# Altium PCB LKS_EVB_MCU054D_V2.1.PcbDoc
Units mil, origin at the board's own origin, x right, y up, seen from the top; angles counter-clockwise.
Board outline 2625 x 1560 mil, 2 copper layers (Top Layer, Bottom Layer); 32 components, 49 nets, 170 pads, 61 vias.
Unrouted connection lines stored in the file: 4.
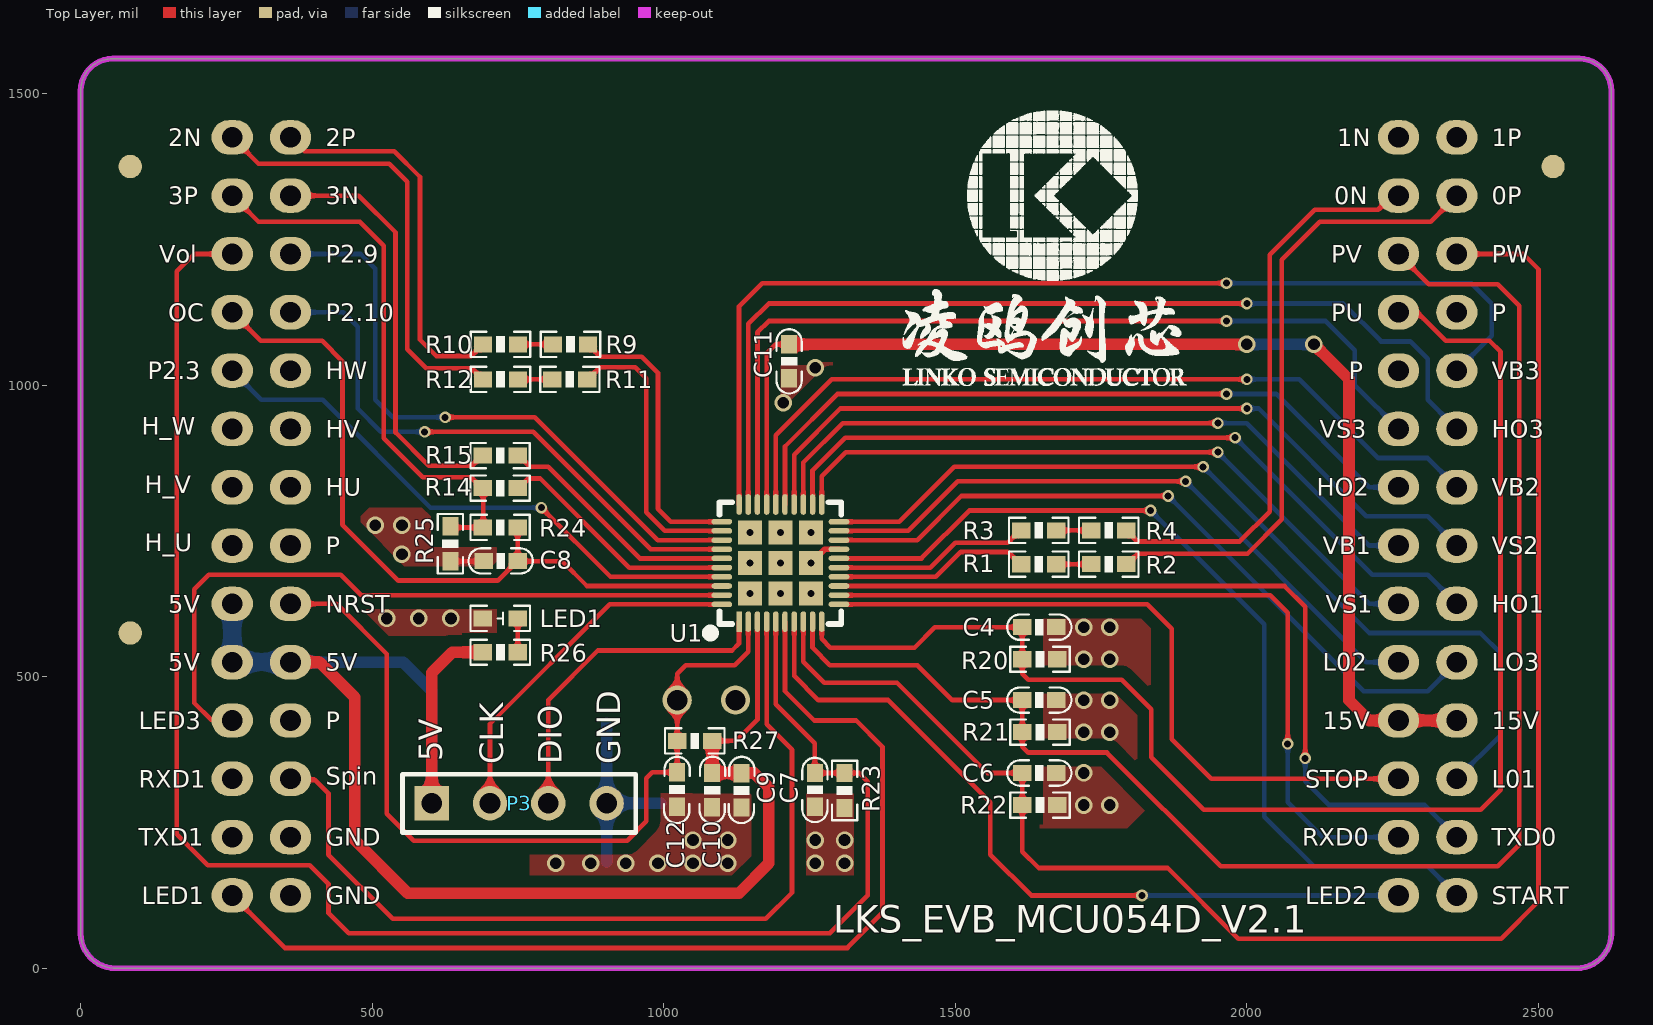
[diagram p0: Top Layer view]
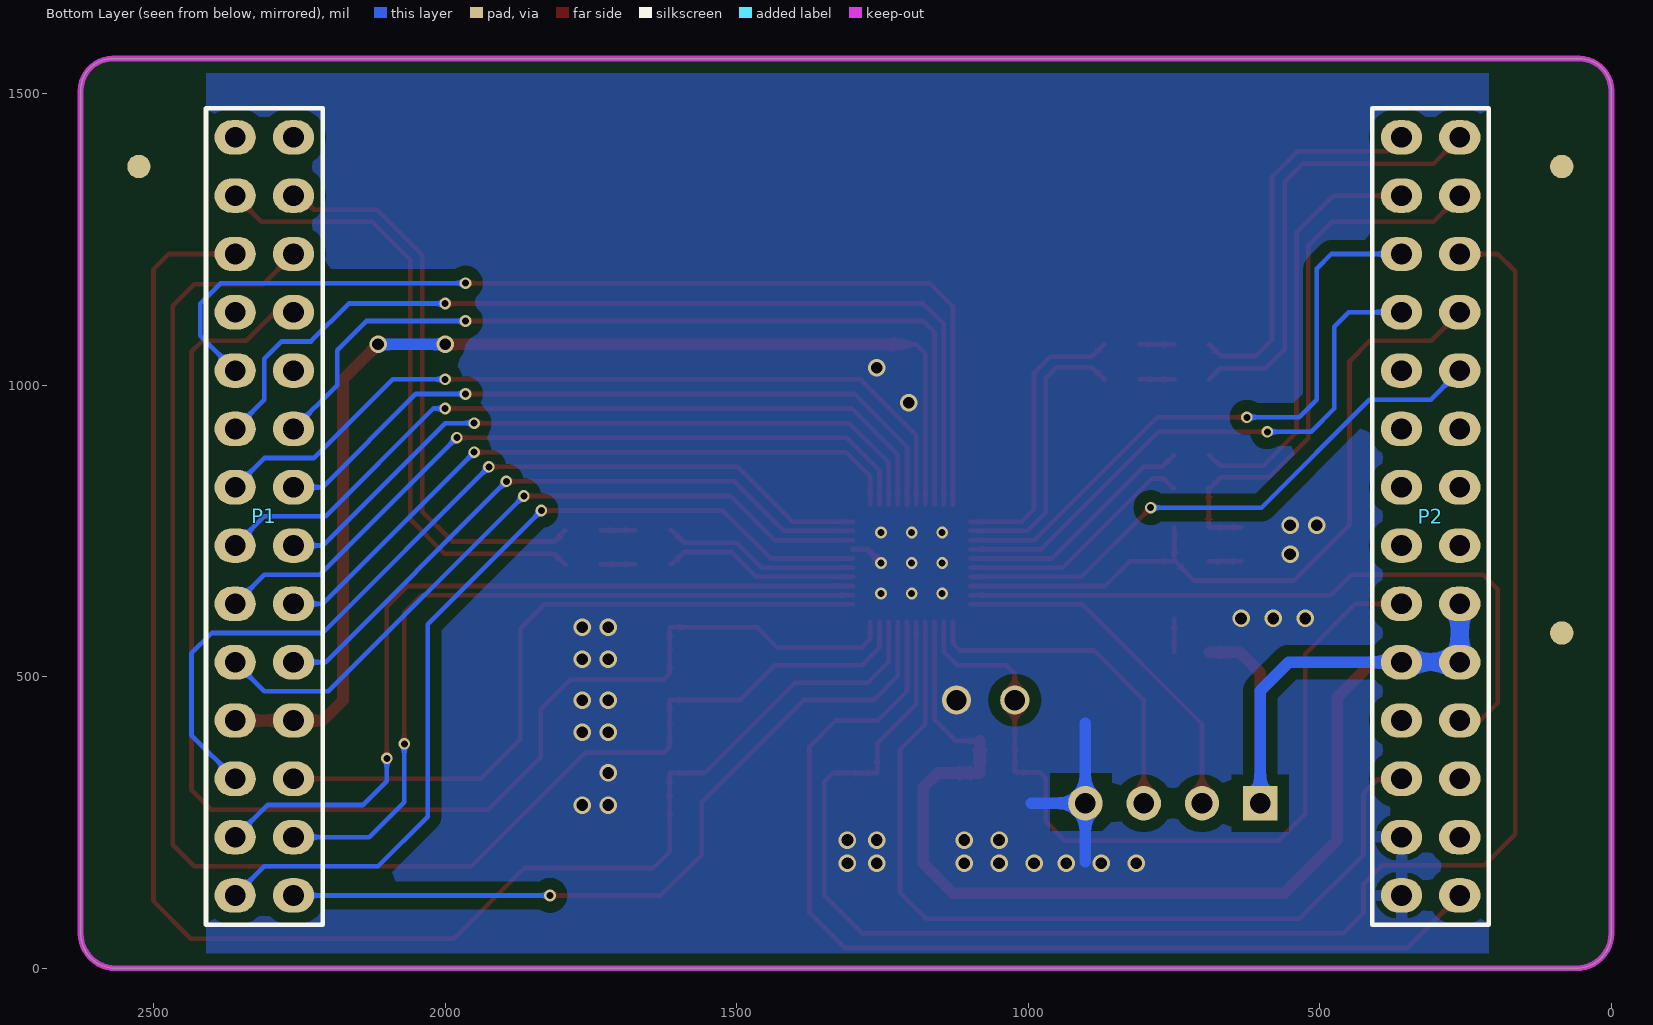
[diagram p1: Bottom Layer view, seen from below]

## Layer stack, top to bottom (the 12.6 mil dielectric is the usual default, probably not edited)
Top Solder: solder mask 0.4, Solder Resist, Dk 3.5
Top Layer: signal copper 1.4
Dielectric1: dielectric 12.6, FR-4, Dk 4.8
Bottom Layer: signal copper 1.4
Bottom Solder: solder mask 0.4, Solder Resist, Dk 3.5

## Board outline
0,60 ccw(c60,60) 60,0 2565,0 ccw(c2565,60) 2625,60 2625,1505 ccw(c2570,1505) 2570,1560 55,1560 ccw(c55,1505) 0,1505

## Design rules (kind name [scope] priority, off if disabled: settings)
Clearance Clearance_1 [InPolygon] p1: gap=20 ignorepadtopadclearanceinfootprint=FALSE except(0: Arc-Hole Track-Hole SMDPad-Hole THPad-Hole Via-Hole Fill-Hole Poly-Hole Region-Hole Text-Hole)
Clearance [All] p2 off: gap=10 ignorepadtopadclearanceinfootprint=FALSE except(0: Arc-Hole Track-Hole SMDPad-Hole THPad-Hole Via-Hole Fill-Hole Poly-Hole Region-Hole Text-Hole)
ComponentClearance [All] p1: gap=0 collisioncheckmode=3 verticalgap=0 showdistances=FALSE
FabricationTestpoint [(IsPad And (OnTopLayer Or OnBottomLayer))] p1: side=3 testpointundercomponent=TRUE minsize=40 maxsize=100 preferedsize=60 minholesize=0 maxholesize=40 preferedholesize=32 testpointgrid=1 allowsidetop=TRUE allowsidebottom=TRUE usegrid=TRUE gridtolerance=0.01
HoleSize [All] p1: absolutevalues=TRUE maxlimit=100 minlimit=0 maxpercent=80.000 minpercent=20.000
PolygonConnect PolygonConnect_1 [HasFootprint('HDR 2X14 顶层') vs InNet('GND')] p1: connectstyle=Relief reliefconductorwidth=20 reliefentries=4 polygonreliefangle="90 Angle" airgapwidth=10
PolygonConnect [All] p2: connectstyle=Direct reliefconductorwidth=30 reliefentries=4 polygonreliefangle="90 Angle" airgapwidth=10
RoutingVias [All] p1: holewidth=28 width=50 viastyle="Through Hole" minholewidth=0 minwidth=10 maxholewidth=28 maxwidth=100
SilkToSolderMaskClearance SilkscreenOverComponentPads [IsPad] p1: minsilkscreentomaskgap=10 clearancetoexposedcopper=TRUE
SolderMaskExpansion [All] p1: expansion=4 istentingtop=FALSE
Width [All] p1: maxlimit=100 minlimit=2 preferedwidth=10
26 further rules are at their usual default settings.

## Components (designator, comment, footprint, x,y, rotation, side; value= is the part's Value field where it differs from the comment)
C4 "1nF/16V" 0603C#1 1644,585 r0 top
C5 "1nF/16V" 0603C#1 1644,460 r0 top
C6 "1nF/16V" 0603C#1 1644,335 r0 top
C7 "100nF/50V" 0603C#1 1259.18,305.95 r90 top
C8 "1nF/50V" 0603C#1 720.35,698.65 r0 top
C9 "10uF/16V" 0603C#2 1133,275.76 r90 top
C10 "100nF/50V" 0603C#2 1083,275.94 r90 top
C11 "4.7uF/25V" 0603C#1 1215,1040.95 r90 top
C12 "100nF/50V" 0603C#2 1023,336 r270 top
LED1 "LED" "LED 0603R" 719.69,600 r180 top
P1 "Header 14X2A" "HDR 2X14 顶层" 2310,775 r180 bottom locked
P2 "Header 14X2A" "HDR 2X14 顶层" 310,775 r180 bottom locked
P3 "Header 4" "HDR 1X4" 602,283 r0 top
R1 "20K" 0603R 1643,692.98 r180 top value=K
R2 "20K" 0603R 1763,693 r180 top value=K
R3 "20K" 0603R 1643,751 r180 top value=K
R4 "20K" 0603R 1763,751 r180 top value=K
R9 "20K" 0603R 839.97,1070.01 r0 top value=K
R10 "20K" 0603R 719.95,1070.01 r0 top value=K
R11 "20K" 0603R 838.95,1010.01 r0 top value=K
R12 "20K" 0603R 719.95,1010.01 r0 top value=K
R14 "1K" 0603R 719.4,823.35 r0 top value=K
R15 "1K" 0603R 719.4,879.35 r0 top value=K
R20 "1K" 0603R 1645,530 r0 top value=K
R21 "1K" 0603R 1645,405 r0 top value=K
R22 "1K" 0603R 1645,280 r0 top value=K
R23 "1K" 0603R 1310,305 r90 top value=K
R24 "1K" 0603R 719.4,756 r180 top value=K
R25 "10R" 0603R 634,727.94 r270 top value=K
R26 "3.3K" 0603R 719.69,542 r180 top value=330
R27 "20K" 0603R 1053,390 r180 top value=330
U1 "LKS32MC054DF6Q8" QFN40 1200,695 r90 top locked

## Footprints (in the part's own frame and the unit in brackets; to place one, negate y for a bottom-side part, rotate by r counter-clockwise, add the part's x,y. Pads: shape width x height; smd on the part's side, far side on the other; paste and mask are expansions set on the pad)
0603C#1 [mm] "电容"
  rect 0.8x0.7 smd: 1(-0.737,0) 2(0.738,0)
  silkscreen extent -1.4,-0.55 1.4,0.55, body extent -0.8,-0.41 0.8,0.41, height 0.81
0603C#2 [mm]
  rect 0.8x0.7 smd: 1(0,0) 2(1.5,0)
  silkscreen extent -0.68,-0.57 2.21,0.55
0603R [mm] "电阻"
  rect 0.8x0.7 smd: 1(-0.762,0) 2(0.762,0)
  silkscreen extent -1.3,-0.55 1.3,0.55, body extent -0.8,-0.4 0.8,0.4, height 0.45
"HDR 1X4" [mm] "单排针 2.54mm"
  rect 1.5x1.5 hole 0.9: 1(0,0)
  round 1.5 hole 0.9: 2(2.54,0) 3(5.08,0) 4(7.62,0)
  silkscreen extent -1.27,-1.27 8.89,1.27, body extent -1.27,-1.27 8.89,1.27, height 8.5
"HDR 2X14 顶层" [mm] "双排针 2.54mm 顶层"
  oval 1.8x1.5 hole 0.9: 1(1.27,16.51) 2(1.27,13.97) 3(1.27,11.43) 4(1.27,8.89) 5(1.27,6.35) 6(1.27,3.81) 7(1.27,1.27) 8(1.27,-1.27) 9(1.27,-3.81) 10(1.27,-6.35) 11(1.27,-8.89) 12(1.27,-11.43) 13(1.27,-13.97) 14(1.27,-16.51) 15(-1.27,16.51) 16(-1.27,13.97) 17(-1.27,11.43) 18(-1.27,8.89) 19(-1.27,6.35) 20(-1.27,3.81) 21(-1.27,1.27) 22(-1.27,-1.27) 23(-1.27,-3.81) 24(-1.27,-6.35) 25(-1.27,-8.89) 26(-1.27,-11.43) 27(-1.27,-13.97) 28(-1.27,-16.51)
  silkscreen extent -2.54,-17.78 2.54,17.78, body extent -2.54,-17.78 2.54,17.78, height 8.5
"LED 0603R" [mm] "LED"
  rect 0.8x0.7 smd: 1(-0.762,0) 2(0.762,0)
  silkscreen extent -1.3,-0.55 1.3,0.55, body extent -0.8,-0.4 0.8,0.4, height 0.47
QFN40 [mm] "LINKO-084D"
  rect 1.05x1.05 smd: 0(-1.33,-1.33) 0(-1.33,0) 0(-1.33,1.33) 0(0,1.33) 0(0,0) 0(0,-1.33) 0(1.33,-1.33) 0(1.33,0) 0(1.33,1.33)
  rect 0.9x0.24 smd: 1(-2.55,1.8)
  oval 0.9x0.24 smd: 2(-2.55,1.4) 3(-2.55,1) 4(-2.55,0.6) 5(-2.55,0.2) 6(-2.55,-0.2) 7(-2.55,-0.6) 8(-2.55,-1) 9(-2.55,-1.4) 10(-2.55,-1.8) 21(2.55,-1.8) 22(2.55,-1.4) 23(2.55,-1) 24(2.55,-0.6) 25(2.55,-0.2) 26(2.55,0.2) 27(2.55,0.6) 28(2.55,1) 29(2.55,1.4) 30(2.55,1.8)
  oval 0.24x0.9 smd: 11(-1.8,-2.55) 12(-1.4,-2.55) 13(-1,-2.55) 14(-0.6,-2.55) 15(-0.2,-2.55) 16(0.2,-2.55) 17(0.6,-2.55) 18(1,-2.55) 19(1.4,-2.55) 20(1.8,-2.55) 31(1.8,2.55) 32(1.4,2.55) 33(1,2.55) 34(0.6,2.55) 35(0.2,2.55) 36(-0.2,2.55) 37(-0.6,2.55) 38(-1,2.55) 39(-1.4,2.55) 40(-1.8,2.55)
  silkscreen extent -3.16,-2.65 2.65,3.16, body extent -3,-3 3,3, height 0.9

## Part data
C4 C5 C6: library part CAP, "Capacitor"
C7 C8 C9 C10 C11 C12: library part C, "Capacitor"
LED1: "LED_Light"
P1 P2: "Header, 14-Pin, Dual row"
P3: "Header, 4-Pin"
R1 R2 R3 R4 R9 R10 R11 R12 R14 R15 R20 R21 R22 R23 R24 R25 R26 R27: library part Res, "Resistor"
U1: "芯片"

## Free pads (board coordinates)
  round 50 hole 35: 0(1123,460) 1(1023,460)
  round 40 all layers, no hole: 1(85,1375) 2(85,575) 3(2525,1375)

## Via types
v1: diameter 30, hole 20, Top Layer to Bottom Layer, 33 vias
v2: diameter 20, hole 12, Top Layer to Bottom Layer, 28 vias

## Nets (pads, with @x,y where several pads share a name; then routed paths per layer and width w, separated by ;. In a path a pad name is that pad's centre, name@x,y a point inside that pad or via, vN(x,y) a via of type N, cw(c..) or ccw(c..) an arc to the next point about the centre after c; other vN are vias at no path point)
+5V: C9.2 C10.2 P2.9 P2.10 P2.24 P3.1 R26.2 R27.1 U1.3 | length 2683.2
  Top Layer w8: R27.1 1124,390 1160.63,426.63 U1.3
  Top Layer w20: P2.24 410,525 470,465 470,220 561,129 1129,129 1180,180 1180,310.26 1155.44,334.82 C9.2 ; P3.1 602,507 637,542 R26.2 ; C10.2 R27.1 ; C10.2@1083.09,334.91 C9.2@1132.91,334.91
  Bottom Layer w20: P2.24 553,525 602,476 P3.1
  Bottom Layer w30: P2.9 P2.10 P2.24
+15V: C11.2 P1.11 P1.25 U1.27 | length 2038.5
  Top Layer w8: U1.27 1176.38,1054.57 1191.81,1070 C11.2
  Top Layer w20: C11.2 v1(2000,1070) ; v1(2115,1070) 2175,1010 2175,460 2210,425 P1.11 P1.25
  Bottom Layer w20: v1(2000,1070) v1(2115,1070)
GND: C4.2 C5.2 C6.2 C7.1 C8.1 C9.1 C10.1 C11.1 C12.2 LED1.2 P2.16 P2.27 P2.28 P3.4 pad.0 R15.1 R20.2 R21.2 R22.2 R23.1 R25.2 U1.0 U1.17 | length 1175.1
  Top Layer w8: P2.16 477,1325 540,1262 540,919 597,862 671.03,862 688.38,879.35 R15.1@690.35,879.35 ; R25.2 690.94,697.94 C8.1@691,698
  Top Layer w10: v2(1252.36,695) 1275.98,718.62 U1.17
  Bottom Layer w20: 902,183 P3.4 ; 902,420 P3.4 ; 995,283 P3.4
  other v1: 815,180 875,180 935,180 990,180 1050,180 1110,180 1260,180 1310,180 1050,220 1110,220 1260,220 1310,220 1720,280 1765,280 1720,335 1720,405 1765,405 1720,460 1765,460 1720,530 1765,530 1720,585 1765,585 525,600 580,600 635,600 551,710 505,760 551,760 1205,970 1260,1030
  other v2: 1147.64,642.64 1200,642.64 1252.36,642.64 1147.64,695 1200,695 1147.64,747.36 1200,747.36 1252.36,747.36
HO1: P1.23 U1.22 | length 1304.8
  Top Layer w8: U1.22 1255.12,854.12 1311,910 v2(1980,910)
  Bottom Layer w8: v2(1980,910) 2215,675 2310,675 P1.23
HO2: P1.7 U1.25 | length 1255.2
  Top Layer w8: U1.25 1207.87,894.87 1298,985 v2(1965,985)
  Bottom Layer w8: v2(1965,985) 2050,985 2210,825 P1.7
HO3: P1.20 U1.29 | length 1669.3
  Top Layer w8: U1.29 1144.88,1105 1179.88,1140 v2(2000,1140)
  Bottom Layer w8: v2(2000,1140) 2165,1140 2230,1075 2280,1075 2310,1045 2310,975 P1.20
LED1: P2.14 U1.6 | length 1788.2
  Top Layer w8: P2.14 350,35 1315,35 1375,95 1375,380 1330,425 1257.87,425 1207.87,475 U1.6
LED2: P1.14 U1.7 | length 1338.2
  Top Layer w8: U1.7 1223.62,501.38 1265,460 1385,460 1560,285 1560,195 1630,125 v2(1820,125)
  Bottom Layer w8: v2(1820,125) P1.14
LED3: P2.11 U1.39 | length 1201.9
  Top Layer w8: P2.11 258.16,426.84 223.16,426.84 195,455 195,650 220,675 446,675 481.12,639.88 U1.39
LO1: P1.26 U1.20 | length 1552.2
  Top Layer w8: U1.20 1403.87,765.87 1498,860 v2(1925,860)
  Bottom Layer w8: v2(1925,860) 2210,575 2400,575 2435,540 2435,400 P1.26
LO2: P1.10 U1.19 | length 1123.2
  Top Layer w8: U1.19 1419.12,750.12 1504,835 v2(1895,835)
  Bottom Layer w8: v2(1895,835) 2205,525 P1.10
LO3: P1.24 U1.18 | length 1250.4
  Top Layer w8: U1.18 1434.37,734.37 1510,810 v2(1865,810)
  Bottom Layer w8: v2(1865,810) 2200,475 2310,475 P1.24
NetLED1_1: LED1.1 R26.1 | length 58
  Top Layer w8: R26.1 LED1.1
NetR1_1: R1.1 R2.2 | length 60
  Top Layer w8: R1.1 R2.2
NetR3_1: R3.1 R4.2 | length 60
  Top Layer w8: R3.1 R4.2
NetR9_1: R9.1 R10.2 | length 59.9
  Top Layer w8: R10.2@749,1070.01 R9.1@808.95,1070.01
NetR11_1: R11.1 R12.2 | length 59.9
  Top Layer w8: R12.2@749,1010.01 R11.1
NRST: C12.1 P2.23 pad.1@1023,460 R27.2 U1.2 | length 1441.8
  Top Layer w8: P2.23 439,625 525,539 525,265 571,219 937,219 970,252 970,326 980,336 C12.1 R27.2 1023,460 1023,505 1038,520 1122,520 1144.88,542.88 U1.2
OC: C8.2 P2.4 R24.1 U1.38 | length 1283.7
  Top Layer w8: P2.4 309,1076 414,1076 449,1041 449,761 545,665 715.09,665 748.09,698 C8.2@750.06,698 ; R24.1 C8.2 C8.2@750.06,698 ; U1.38 868.37,655.63 826,698 C8.2@750.06,698
OPA0_IN: R11.2 U1.32 | length 492
  Top Layer w8: R11.2@869,1009.35 868.35,1010.01 869.97,1010.01 890.97,1031.01 950.99,1031.01 970,1012 970,782 1001.88,750.12 U1.32
OPA0_IP: R9.2 U1.31 | length 492.1
  Top Layer w8: R9.2 890.97,1049.01 961.99,1049.01 990,1021 990,788 1012.13,765.87 U1.31
OPA1_IN: R15.2 U1.35 | length 423.3
  Top Layer w8: R15.2 751.37,879.35 770.72,860 802,860 880.56,781.44 959.13,702.87 U1.35
OPA1_IP: R14.2 U1.36 | length 420.4
  Top Layer w8: R14.2 751.37,823.35 768.02,840 788,840 940.87,687.13 U1.36
OPA2_IN: R3.2 U1.15 | length 339.1
  Top Layer w8: U1.15 1457.13,687.13 1500,730 1590.03,730 1611.03,751 R3.2
OPA2_IP: R1.2 U1.14 | length 339
  Top Layer w8: U1.14 1466.38,671.38 1509,714 1590.01,714 1611.03,692.98 R1.2
P2.3: P2.5 U1.37 | length 986.1
  Top Layer w8: v2(790,790) 908.62,671.38 U1.37
  Bottom Layer w8: P2.5 310,975 415,975 600,790 v2(790,790)
P2.9: P2.17 U1.33 | length 1074.6
  Top Layer w8: v2(625,945) 779,945 989.63,734.37 U1.33
  Bottom Layer w8: P2.17 480,1225 505,1200 505,975 535,945 v2(625,945)
P2.10: P2.18 U1.34 | length 989.9
  Top Layer w8: v2(590,920) 776,920 977.38,718.62 U1.34
  Bottom Layer w8: P2.18 450,1125 475,1100 475,960 515,920 v2(590,920)
PGND: P1.1 P1.2 P2.1 P2.2 R4.1 R12.1 R14.1 R24.2 R25.1 | length 2707.9
  Top Layer w8: P2.2 305,1280 479,1280 520,1239 520,909 587,842 669.73,842 688.38,823.35 690.35,823.35 692.32,823.35 690.35,821.38 690.35,756 635,756 R25.1@634,757 ; P2.1 305,1380 529,1380 560,1349 560,1062 592.99,1029.01 670.95,1029.01 R12.1 ; R4.1 1794.97,751 1804.75,741.22 1804.75,739.25 1812,732 1987.69,732 2039,783.31 2039,1223.7 2116.3,1301 2225,1301 2249,1325 P1.2
PU: C4.1 P1.4 R20.1 U1.10 | length 2407.2
  Top Layer w8: U1.10 1270.87,565 1285.87,550 1430,550 1465,585 C4.1 R20.1 1615,505 1625,495 1785,495 1836,444 1836,362 1926,272 2401,272 2435,306 2435,1057 2416,1076 2341,1076 2292,1125 P1.4
PV: C5.1 P1.3 R21.1 U1.9 | length 2641.9
  Top Layer w8: U1.9 1255.12,549.88 1285,520 1435,520 1495,460 C5.1 R21.1 1615,380 1625,370 1760,370 1955,175 2430,175 2467,212 2467,1136 2430,1173 2312,1173 P1.3
PW: C6.1 P1.17 R22.1 U1.8 | length 2866.6
  Top Layer w8: U1.8 1239.37,525.63 1275,490 1400,490 1555,335 C6.1 R22.1 1615,200 1643,172 1864,172 1985,51 2436,51 2500,115 2500,1199 2474,1225 P1.17
RXD0: P1.13 U1.12 | length 1321.8
  Top Layer w8: U1.12 2040.12,639.88 2070,610 v2(2070,385)
  Bottom Layer w8: v2(2070,385) 2070,285 2130,225 P1.13
SPIN: P2.26 U1.4 | length 1522.2
  Top Layer w8: P2.26 361.53,323.47 401.53,323.47 425,300 425,195 535,85 1175,85 1220,130 1220,375 1176.38,418.62 U1.4
START1: P1.28 U1.16 | length 1560.3
  Top Layer w8: U1.16 1441.87,702.87 1524,785 v2(1835,785)
  Bottom Layer w8: v2(1835,785) 2030,590 2030,260 2115,175 2310,175 P1.28
STOP1: P1.12 U1.11 | length 1194.2
  Top Layer w8: U1.11 1828.87,624.13 1871,582 1871,393 1939,325 P1.12
SWCLK: P3.2 U1.40 | length 618.6
  Top Layer w8: P3.2 702,419.01 907.13,624.13 U1.40
SWDIO: P3.3 U1.1 | length 581.8
  Top Layer w8: P3.3 802,460 887,545 1117,545 1129.13,557.13 U1.1
TXD0: P1.27 U1.13 | length 1413.1
  Top Layer w8: U1.13 2064.37,655.63 2100,620 v2(2100,360)
  Bottom Layer w8: v2(2100,360) 2100,321 2141,280 2305,280 P1.27
UP-: P2.15 R10.1 | length 657
  Top Layer w8: P2.15 384,1401 538,1401 582,1357 582,1078 609.99,1050.01 669.95,1050.01 R10.1
VB1: P1.8 U1.23 | length 1207.6
  Top Layer w8: U1.23 1239.37,867.37 1307,935 v2(1950,935)
  Bottom Layer w8: v2(1950,935) 2000,935 2210,725 P1.8
VB2: P1.21 U1.26 | length 1402.9
  Top Layer w8: U1.26 1192.13,914.13 1288,1010 v2(2000,1010)
  Bottom Layer w8: v2(2000,1010) 2090,1010 2225,875 2310,875 P1.21
VB3: P1.19 U1.30 | length 1801.4
  Top Layer w8: U1.30 1129.13,1135 1169.13,1175 v2(1965,1175)
  Bottom Layer w8: v2(1965,1175) 2385,1175 2420,1140 2420,1085 P1.19
VOL_ADC: C7.2 P2.3 R23.2 U1.5 | length 2963.5
  Top Layer w8: P2.3 195,1225 165,1195 165,230 218,177 393,177 425,145 425,95 460,60 1285,60 1350,125 1350,320 1335,335 R23.2 C7.2 1259.18,385.82 1192.13,452.87 U1.5
VP-: P1.15
VS1: P1.9 U1.21 | length 1162.3
  Top Layer w8: U1.21 1270.87,843.87 1312,885 v2(1950,885)
  Bottom Layer w8: v2(1950,885) 2210,625 P1.9
VS2: P1.22 U1.24 | length 1351.8
  Top Layer w8: U1.24 1223.62,880.62 1303,960 v2(2000,960)
  Bottom Layer w8: v2(2000,960) 2020,960 2205,775 2310,775 P1.22
VS3: P1.6 U1.28 | length 1514.4
  Top Layer w8: U1.28 1160.63,1090.63 1180,1110 v2(1965,1110)
  Bottom Layer w8: v2(1965,1110) 2135,1110 2185,1060 2185,1000 P1.6
WP-: P1.16 R2.1 | length 1089.5
  Top Layer w8: R2.1 1794.97,693 1812.97,711 2001,711 2060,770 2060,1215 2125,1280 2315,1280 P1.16
pads on no net: P1.5 P1.18 P2.6 P2.7 P2.8 P2.12 P2.13 P2.19 P2.20 P2.21 P2.22 P2.25

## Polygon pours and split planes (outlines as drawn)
GND on Top Layer "10" (solid, remove dead copper, pour order 21): 715,570 520,570 480,610 480,775 495,790 585,790 600,775 600,740 612.06,727.94 707.2,727.94 720.35,714.8 720.35,714.79 720.35,575.35
GND on Top Layer "10" (solid, remove dead copper, pour order 17): 770,220 770,130 1130,130 1180,180 1180,305 986,305 970,289 970,252 937,219 936,220
GND on Top Layer "10" (solid, remove dead copper, pour order 20): 1201.09,1048.51 1192.58,1040 1180,1040 1180,1035 1175,1030 1175,955 1185,945 1223,945 1290,1012 1290,1045 1286.49,1048.51
GND on Top Layer "10" (solid, remove dead copper, pour order 19): 1645,240 1795,240 1835,280 1835,585 1795,625 1665,625 1645,605 1645,250
GND on Top Layer "10" (solid, remove dead copper, pour order 18): 1220,160 1350,160 1350,300 1344.06,305.94 1230.94,305.94 1220,295
GND on Bottom Layer "Top Layer-No Net 1" (solid, remove dead copper, pour order 15): 210,1560 210,0 2410,0 2410,1560

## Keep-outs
Keep-Out Layer:
  the board outline again, w10

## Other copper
Top Layer:
  pour cut-out: 499,525 590,525 590,509 586,505 499,505
Bottom Layer:
  pour cut-out: 856,335 856,254 855,253 873,235 963,235 963,335
  pour cut-out: 303,1384 406,1384 410,1380 410,1266 313,1266 304,1275

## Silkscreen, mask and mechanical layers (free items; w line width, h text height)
Top Overlay:
  drawing of 144 lines, arcs and shapes, not listed
  text "2N" at 150,1410 h30
  text "2P" at 420,1410 h30
  text "1N" at 2155,1410 h30
  text "1P" at 2420,1410 h30
  text "3P" at 150,1310 h30
  text "3N" at 420,1310 h30
  text "0N" at 2150,1310 h30
  text "0P" at 2420,1310 h30
  text "Vol" at 135,1210 h30
  text "P2.9" at 420,1210 h30
  text "PV" at 2145,1210 h30
  text "PW" at 2420,1210 h30
  text "OC" at 150,1110 h30
  text "P2.10" at 420,1110 h30
  text "PU" at 2145,1110 h30
  text "P" at 2420,1110 h30
  text "P2.3" at 115,1010 h30
  text "HW" at 420,1010 h30
  text "P" at 2175,1010 h30
  text "VB3" at 2420,1010 h30
  text "H_W" at 105,915 h30
  text "HV" at 420,910 h30
  text "VS3" at 2125,910 h30
  text "HO3" at 2420,910 h30
  text "H_V" at 110,815 h30
  text "HU" at 420,810 h30
  text "HO2" at 2120,810 h30
  text "VB2" at 2420,810 h30
  text "H_U" at 110,715 h30
  text "P" at 420,710 h30
  text "VB1" at 2130,710 h30
  text "VS2" at 2420,710 h30
  text "5V" at 150,610 h30
  text "NRST" at 420,610 h30
  text "VS1" at 2135,610 h30
  text "HO1" at 2420,610 h30
  text "5V" at 150,510 h30
  text "5V" at 420,510 h30
  text "L02" at 2130,510 h30
  text "LO3" at 2420,510 h30
  text "LED3" at 100,410 h30
  text "P" at 420,410 h30
  text "15V" at 2130,410 h30
  text "15V" at 2420,410 h30
  text "5V" at 620,355 h40 r90
  text "CLK" at 725,350 h40 r90
  text "DIO" at 825,350 h40 r90
  text "GND" at 925,350 h40 r90
  text "Spin" at 420,315 h30
  text "RXD1" at 100,310 h30
  text "STOP" at 2100,310 h30
  text "L01" at 2420,310 h30
  text "TXD1" at 100,210 h30
  text "GND" at 420,210 h30
  text "RXD0" at 2095,210 h30
  text "TXD0" at 2420,210 h30
  text "LED1" at 105,110 h30
  text "GND" at 420,110 h30
  text "LED2" at 2100,110 h30
  text "START" at 2420,110 h30
  text "LKS_EVB_MCU054D_V2.1" at 1291,46 h80
Top Solder:
  circle w78: c2525,1375 r17
  circle w78: c85,575 r17
  circle w78: c85,1375 r17
Mechanical 1:
  the board outline again, w10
